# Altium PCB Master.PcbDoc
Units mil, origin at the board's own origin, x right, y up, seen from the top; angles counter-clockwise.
Board outline 3120.03 x 2730.03 mil, 2 copper layers (Top Layer, Bottom Layer); 69 components, 56 nets, 304 pads, 108 vias.
Unrouted connection lines stored in the file: 2.
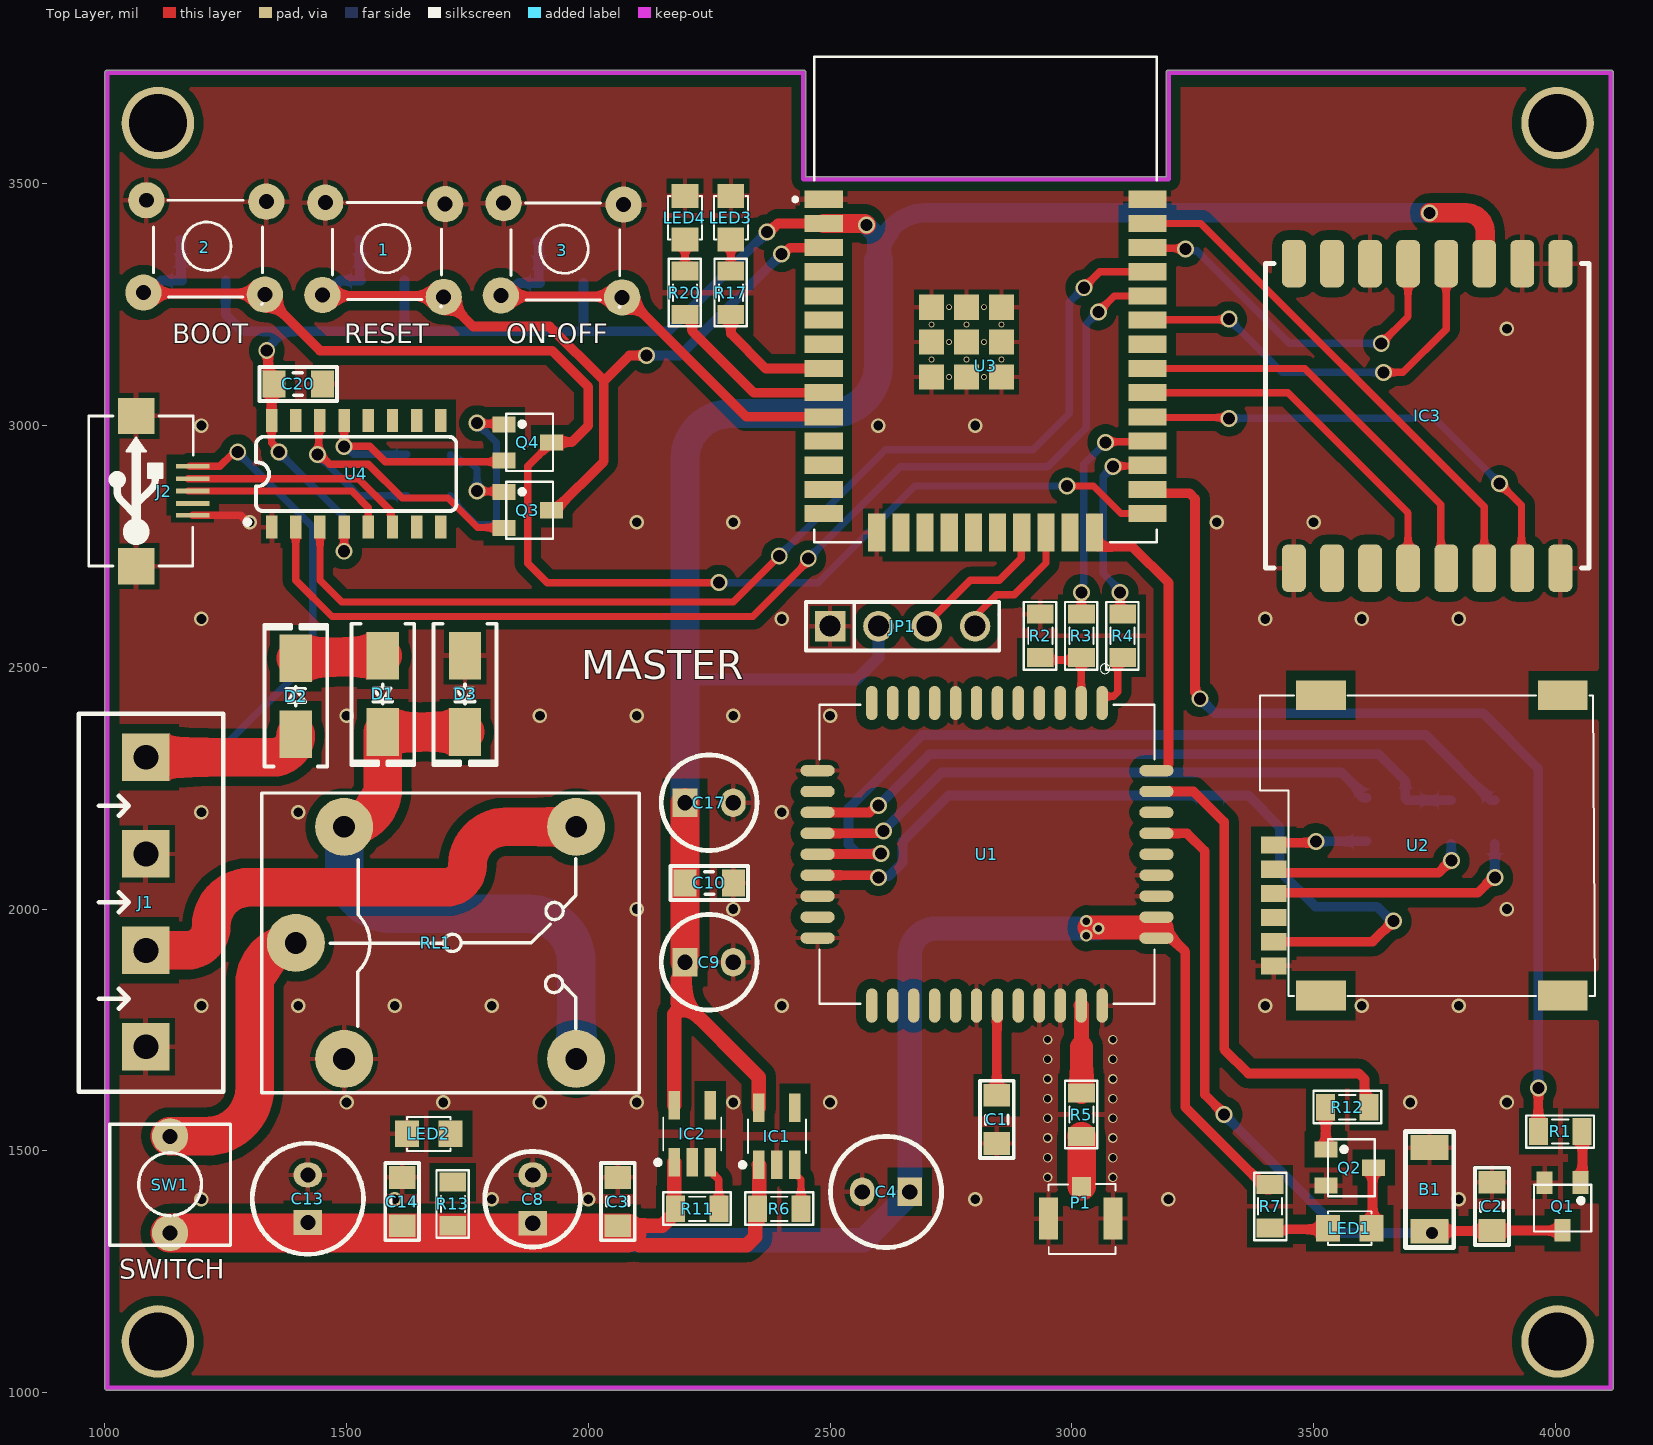
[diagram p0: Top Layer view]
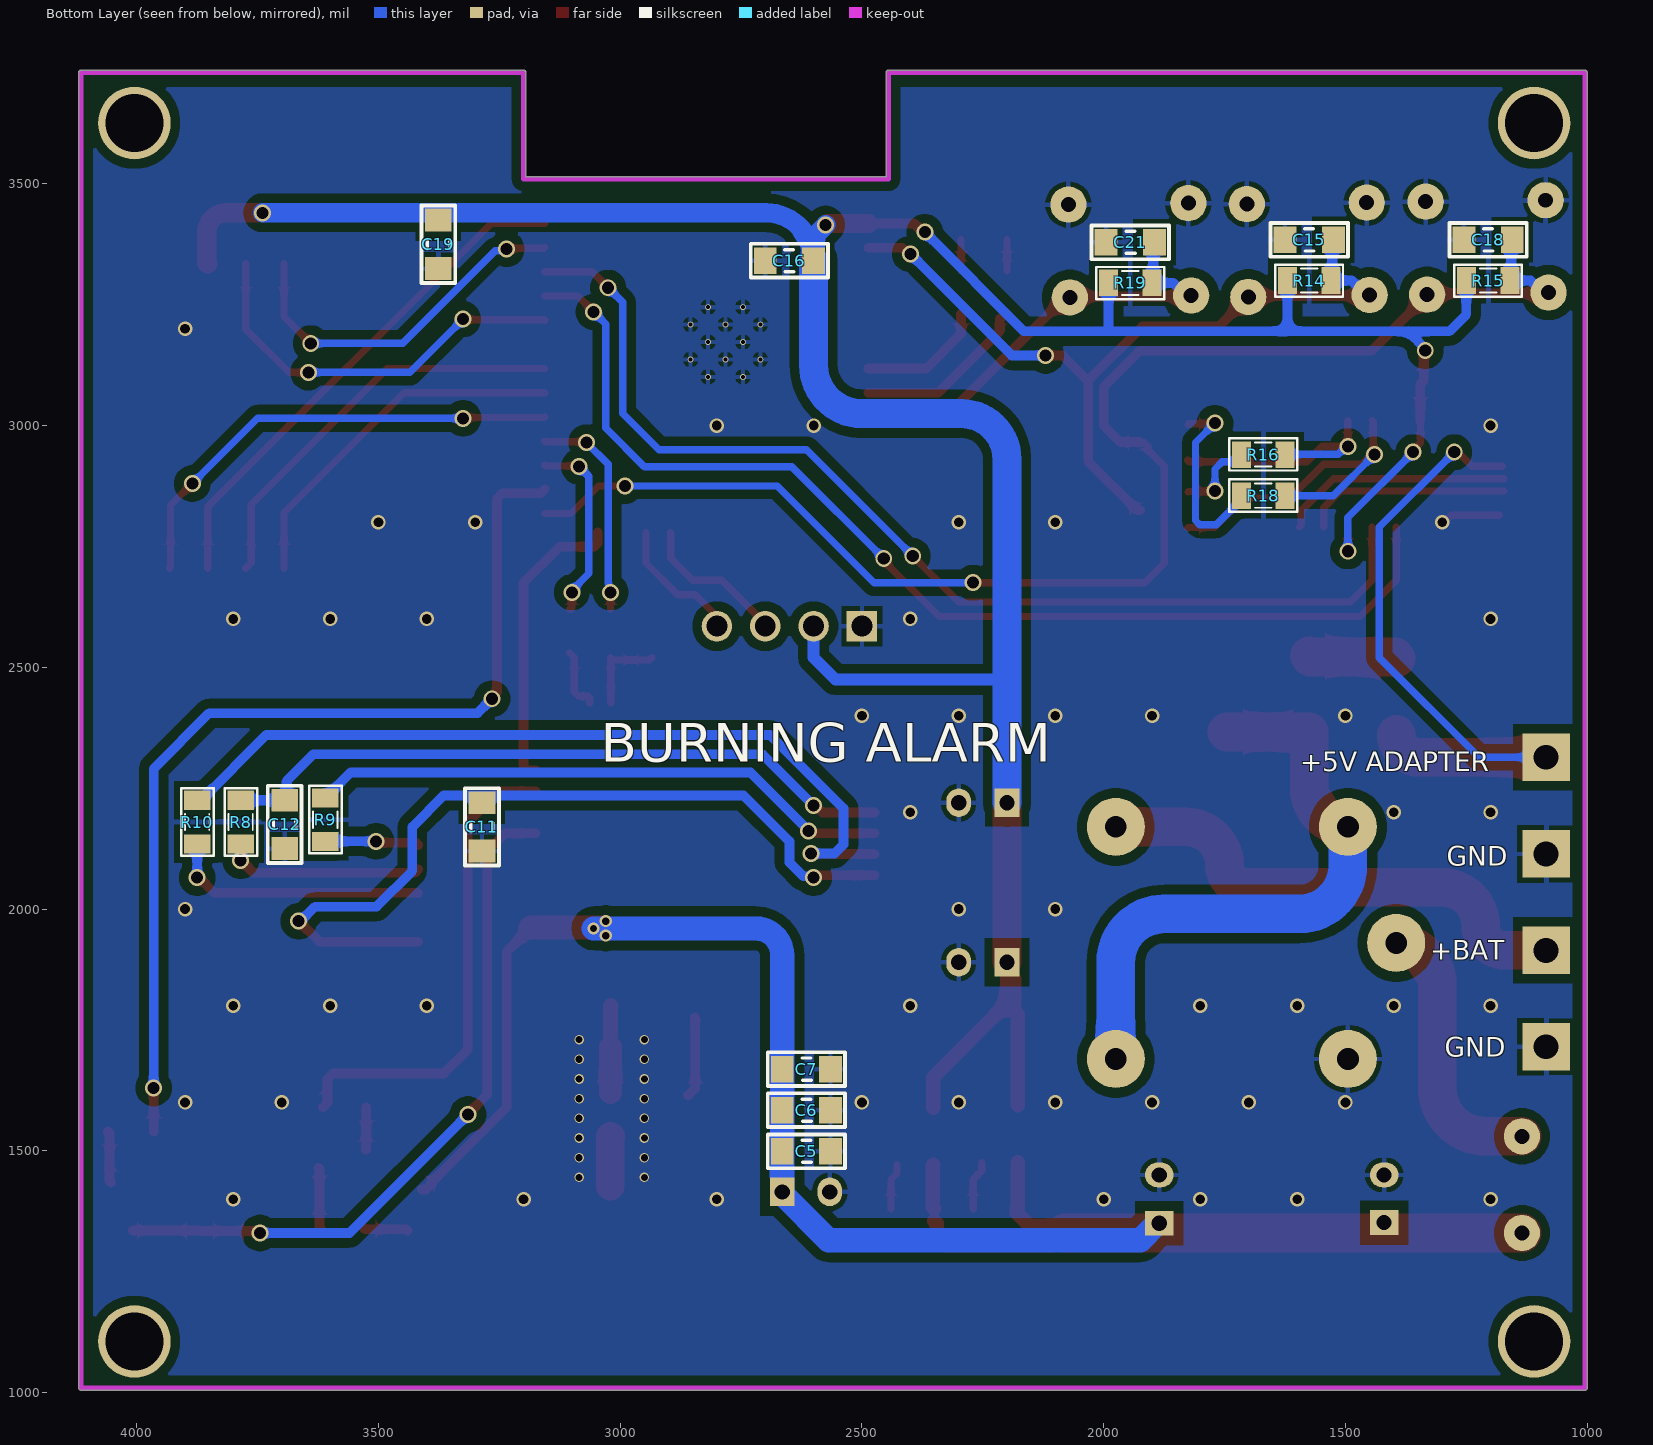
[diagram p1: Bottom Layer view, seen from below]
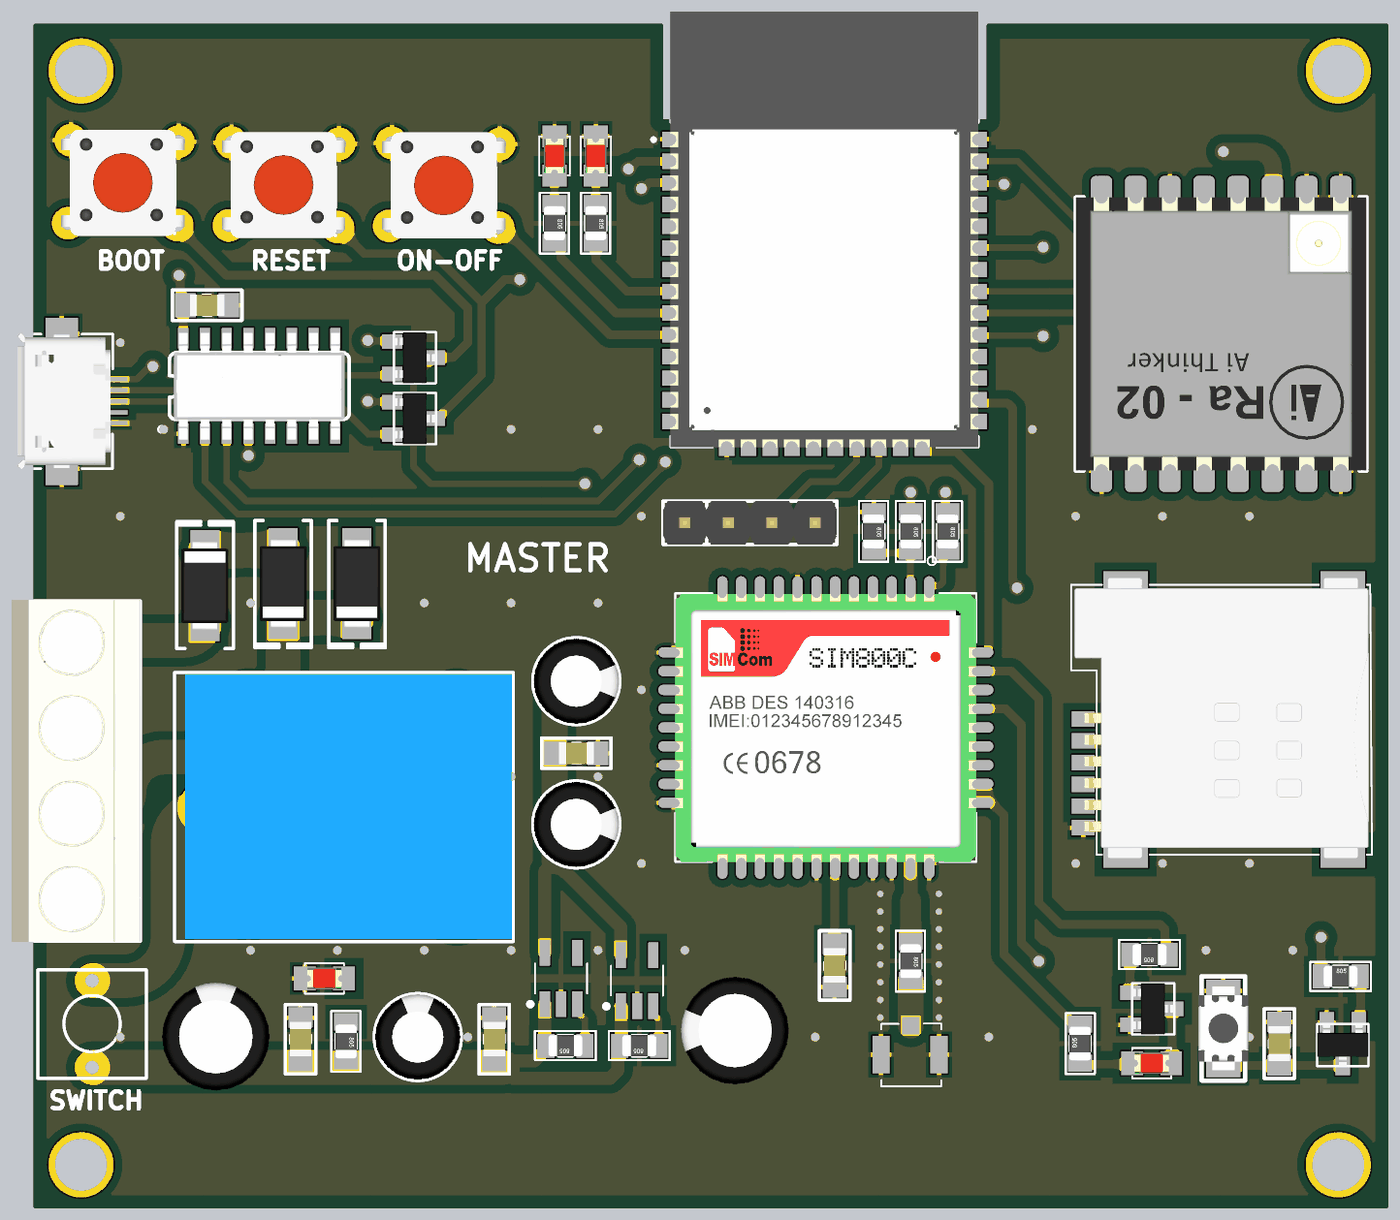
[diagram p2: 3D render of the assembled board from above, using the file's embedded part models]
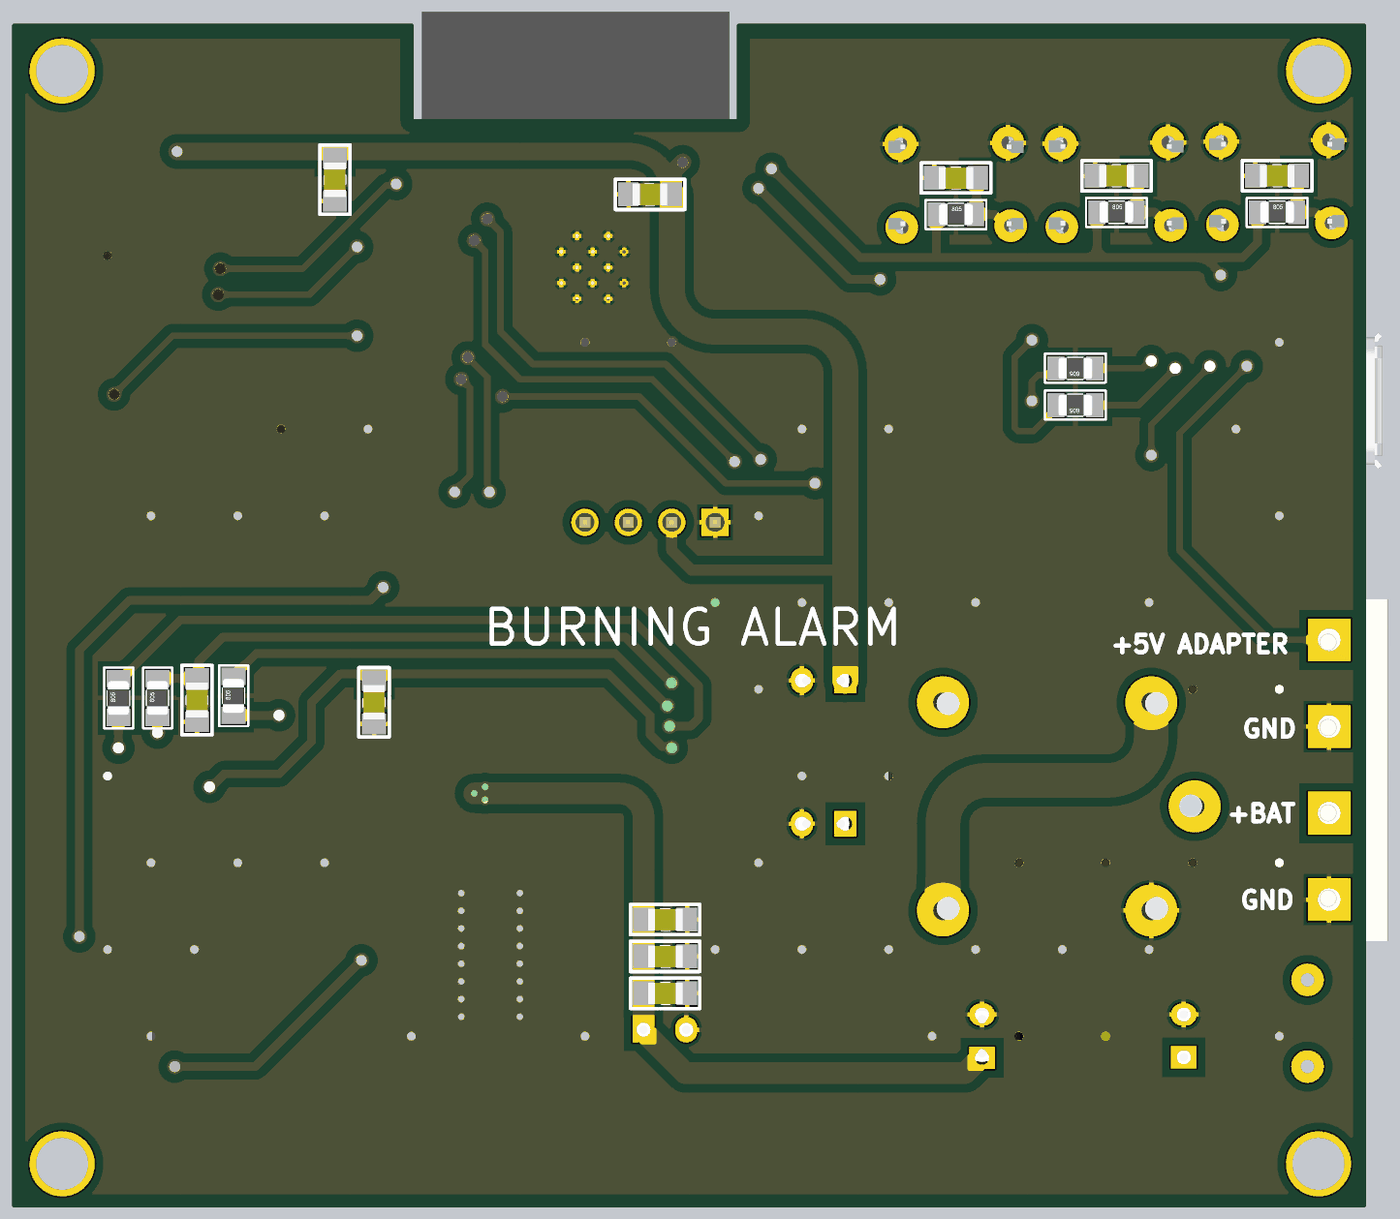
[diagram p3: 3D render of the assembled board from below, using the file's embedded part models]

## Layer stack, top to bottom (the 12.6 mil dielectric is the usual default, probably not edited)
Top Solder: solder mask 0.4, Solder Resist, Dk 3.5
Top Layer: signal copper 1.4
Dielectric 1: dielectric 12.6, FR-4, Dk 4.8
Bottom Layer: signal copper 1.4
Bottom Solder: solder mask 0.4, Solder Resist, Dk 3.5

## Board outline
999.99,1010 999.99,3730 cw(c1005,3730) 1005,3735.01 2160,3735.02 2445,3735.02 cw(c2445,3730) 2450.01,3730 2450.01,3515.01 3194.99,3515.01 3194.99,3730 cw(c3200,3730) 3200,3735.02 4115,3735.02 cw(c4115,3730) 4120.02,3730 4120.02,1010 cw(c4115,1010) 4115,1004.99 1005,1004.99 cw(c1005,1010)

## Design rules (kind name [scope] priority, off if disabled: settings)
Clearance [All] p1: gap=10 ignorepadtopadclearanceinfootprint=FALSE
PolygonConnect [All] p1: thpad.connectstyle=Relief thpad.reliefconductorwidth=10 thpad.reliefentries=4 thpad.polygonreliefangle="90 Angle" thpad.airgapwidth=10 smdpad.connectstyle=Relief smdpad.reliefconductorwidth=10 smdpad.reliefentries=4 smdpad.polygonreliefangle="90 Angle" smdpad.airgapwidth=10 via.connectstyle=Direct via.reliefconductorwidth=10 via.reliefentries=4 via.polygonreliefangle="90 Angle" via.airgapwidth=10
RoutingVias [All] p1: holewidth=20 width=30 viastyle="Through Hole" minholewidth=15 minwidth=15 maxholewidth=30 maxwidth=40
SolderMaskExpansion [All] p1: expansion=4 istentingtop=FALSE
Width [All] p1: maxlimit=100 minlimit=10 preferedwidth=15
30 further rules are at their usual default settings.

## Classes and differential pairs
component class Master: 1 2 3 B1 C1 C2 C3 C4 C5 C6 C7 C8 C9 C10 C11 C12 C13 C14 C15 C18 C20 D1 D2 D3 IC1 IC2 IC3 J1 J2 JP1 LED1 LED2 LED3 LED4 P1 Q1 Q2 Q3 Q4 R1 R2 R3 R4 R5 R6 R7 R8 R9 R10 R11 R12 R13 R14 R15 R16 R17 R18 R19 R20 RL1 SW1 U1 U2 U3 U4

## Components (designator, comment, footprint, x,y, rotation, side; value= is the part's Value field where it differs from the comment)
1 "SW" SW4 1456,3461 r0 top value="Button chip 4 pin"
2 "SW" SW4 1086,3466 r0 top value="Button chip 4 pin"
3 "SW" SW4 1825,3460 r0 top value="Button chip 4 pin"
B1 "Button 3x4x2.5" "Button 3x4x2.5" 3740,1420 r270 top
C1 "10nF" CAP_0805 2846,1565 r270 top value=33p
C2 "100nF" CAP_0805 3870,1385 r270 top value=33p
C3 "100nF" CAP_0805 2060,1395 r90 top value=33p
C4 "470uF" C8mm 2615.79,1415 r180 top
C5 "1uF" CAP_0805 2615,1500 r180 bottom value=33p
C6 "33pF" CAP_0805 2615,1585 r180 bottom value=33p
C7 "10pF" CAP_0805 2615,1670 r180 bottom value=33p
C8 "100uF" C5mm 1885,1400 r90 top
C9 "100uF" C5mm 2250,1890 r0 top
C10 "100nF" CAP_0805 2250,2055 r0 top value=33p
C11 "100nF" CAP_0805 3285,2170 r270 bottom value=33p
C12 "22pF" CAP_0805 3695,2175 r90 bottom value=33p
C13 "470uF" C8mm 1420,1400.79 r90 top
C14 "100nF" CAP_0805 1614,1395 r90 top value=33p
C15 "100nF" CAP_0805 1575,3385 r180 bottom value=33p
C16 "100nF" CAP_0805 2650,3340 r0 bottom value=33p
C17 "100uF" C5mm 2250,2220 r0 top
C18 "100nF" CAP_0805 1205,3385 r180 bottom value=33p
C19 "100nF" CAP_0805 3375,3375 r270 bottom value=33p
C20 "100nF" CAP_0805 1400,3085 r180 top value=33p
C21 "100nF" CAP_0805 1945,3380 r180 bottom value=33p
D1 "SS34 Diode 3A 40V" "DIODE SMA" 1575,2445 r270 top
D2 "SS34 Diode 3A 40V" "DIODE SMA" 1395,2440 r90 top
D3 "M7" "DIODE SMA" 1745,2445 r270 top
IC1 "RT9013" SOT23-5 2390,1530 r90 top
IC2 "RT9013" SOT23-5 2215,1535 r90 top
IC3 "LoRa-02" LoRa-02 3735,3020 r270 top
J1 "KF4" KF4-5.08 1085,2314 r270 top
J2 "USB-5" USB-M1 1181.84,2864.49 r90 top
JP1 "JP 1x4 2.54" "JP 1x4 DT" 2500,2585 r0 top
LED1 "LED" LED-0805-Red 3530,1340 r0 top value="LED 3 ly Single Colour"
LED2 "LED" LED-0805-Red 1715,1535 r180 top value="LED 3 ly Single Colour"
LED3 "LED-WIFI" LED-0805-Red 2295,3385 r90 top value="LED 3 ly Single Colour"
LED4 "LED-ONOFF" LED-0805-Red 2200,3385 r90 top value="LED 3 ly Single Colour"
P1 "Antenna" IPXS 3020,1410 r90 top
Q1 "C1815" SOT23D 4015,1385 r180 top
Q2 "C1815" SOT23D 3575,1465 r270 top
Q3 "C1815" SOT23D 1875,2825 r270 top
Q4 "C1815" SOT23D 1875,2965 r270 top
R1 "10k" RES-SMD-0805 4010,1540 r0 top
R2 "5.6k" RES-SMD-0805 2935,2565 r270 top
R3 "1k" RES-SMD-0805 3020,2565 r270 top
R4 "1k" RES-SMD-0805 3105,2565 r270 top
R5 "0R" RES-SMD-0805 3020,1575 r270 top
R6 "10k" RES-SMD-0805 2395,1380 r180 top
R7 "1k" RES-SMD-0805 3410,1385 r90 top
R8 "51R" RES-SMD-0805 3785,2180 r90 bottom
R9 "51R" RES-SMD-0805 3610,2185 r90 bottom
R10 "51R" RES-SMD-0805 3875,2180 r90 bottom
R11 "10k" RES-SMD-0805 2225,1380 r180 top
R12 "1k" RES-SMD-0805 3570,1590 r180 top
R13 "1k" RES-SMD-0805 1720,1390 r270 top
R14 "10k" RES-SMD-0805 1575,3300 r180 bottom
R15 "10k" RES-SMD-0805 1205,3300 r180 bottom
R16 "10k" RES-SMD-0805 1670,2940 r0 bottom
R17 "1k" RES-SMD-0805 2295,3275 r270 top
R18 "10k" RES-SMD-0805 1670,2855 r0 bottom
R19 "10k" RES-SMD-0805 1945,3295 r180 bottom
R20 "1k" RES-SMD-0805 2200,3275 r270 top
RL1 "Relay 10A/12V" "RELAY 5" 1720,1930 r0 top value="Relay SPDT, 10A, 12V"
SW1 "SW" SW2 1135,1530 r270 top value="SW chip 2 pin"
U1 "SIM800C" SIM800C 2830.43,2123.43 r270 top
U2 "SIM-KF016" "Sim Socket" 3720,2135 r90 top value="Sim holder"
U3 "ESP32-WROOM-32" MODULE_ESP32-WROOM-32 2821.61,3260.94 r0 top
U4 "CH340C" SO016 1520,2900.24 r0 top

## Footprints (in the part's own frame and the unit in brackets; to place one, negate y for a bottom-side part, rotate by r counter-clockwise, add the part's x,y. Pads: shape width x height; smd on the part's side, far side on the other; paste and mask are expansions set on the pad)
"Button 3x4x2.5" [mm]
  rect 1.3x2 smd: 1(-2.2,0) 2(2.2,0)
  silkscreen extent -3.05,-1.27 3.05,1.27, body extent -2.45,-1.45 2.45,1.45, height 2
C5mm [mm]
  rect 1.3x1.5 hole 0.8: 1(-1.27,0)
  oval 1.3x1.5 hole 0.8: 2(1.27,0)
  silkscreen extent -2.51,-2.51 2.51,2.51, body extent -2.5,-2.5 2.49,2.5, height 11.01
C8mm [mm]
  rect 1.3x1.5 hole 0.8: 1(-1.25,0)
  oval 1.3x1.5 hole 0.8: 2(1.25,0)
  silkscreen extent -2.92,-2.92 2.92,2.92, body extent -3.15,-3.15 3.16,3.15, height 11.51
CAP_0805 [mm]
  rect 1.2x1.4 smd: 1(-1.27,-0.025) 2(1.27,-0.025)
  silkscreen extent -2.03,-0.91 2.03,0.86, body extent -1.01,-0.66 1.01,0.61, height 0.61
"DIODE SMA" [mm] "SMA"
  rect 2.5x1.7 smd: 1(-2,0) 2(2,0)
  silkscreen extent -3.68,-1.65 3.75,1.65, body extent -2.6,-1.37 2.6,1.37, height 2.4
IPXS [mm] "SOT 23 _ 1-3-2"
  rect 1x1 smd: 1(0.415,-0.01)
  rect 2.2x1 smd: 2(-1.273,-1.658) 3(-1.278,1.73)
  silkscreen extent -3.13,-1.79 0.53,1.73, body extent -2.83,-1.49 0.31,1.56, height 1.55
"JP 1x4 DT" [mm] "4 pins, 1 row, straight, gold plating"
  rect 1.6x1.6 hole 1.1: 1(0,0)
  round 1.6 hole 1.1: 2(2.54,0) 3(5.08,0) 4(7.62,0)
  silkscreen extent -1.27,-1.27 8.89,1.27, body extent -1.27,-1.27 8.89,1.27, height 8.54
KF4-5.08 [mm]
  rect 2.5x2.5 hole 1.3: 1(0,0) 2(5.08,0) 3(10.147,0) 4(15.215,0)
  silkscreen extent -2.29,-3.53 17.58,4.06, body extent -2.36,-3.43 17.64,4.07, height 10
LED-0805-Red [mil]
  rect 50x55 smd: 1(0,0) 2(90,0)
  silkscreen extent 0,-35 90,35, body extent 5,-25 85,25, height 43
LoRa-02 [mm]
  rrect50% 2.5x1.25 smd: 1(-8,7) 2(-8,5) 2(-8,-3) 3(-8,3) 4(-8,1) 5(-8,-1) 7(-8,-5) 8(-8,-7) 9(8,-7) 10(8,-5) 11(8,-3) 12(8,-1) 13(8,1) 14(8,3) 15(8,5) 16(8,7)
  silkscreen extent -8,-8.5 8,8.5, body extent -8,-8.5 8,8.5, height 3.03
MODULE_ESP32-WROOM-32 [mm]
  rect 2x0.9 smd: 1(-8.5,5.26) 2(-8.5,3.99) 3(-8.5,2.72) 4(-8.5,1.45) 5(-8.5,0.18) 6(-8.5,-1.09) 7(-8.5,-2.36) 8(-8.5,-3.63) 9(-8.5,-4.9) 10(-8.5,-6.17) 11(-8.5,-7.44) 12(-8.5,-8.71) 13(-8.5,-9.98) 14(-8.5,-11.25) 25(8.5,-11.25) 26(8.5,-9.98) 27(8.5,-8.71) 28(8.5,-7.44) 29(8.5,-6.17) 30(8.5,-4.9) 31(8.5,-3.63) 32(8.5,-2.36) 33(8.5,-1.09) 34(8.5,0.18) 35(8.5,1.45) 36(8.5,2.72) 37(8.5,3.99) 38(8.5,5.26)
  rect 0.9x2 smd: 15(-5.715,-12.25) 16(-4.445,-12.25) 17(-3.175,-12.25) 18(-1.905,-12.25) 19(-0.635,-12.25) 20(0.635,-12.25) 21(1.905,-12.25) 22(3.175,-12.25) 23(4.445,-12.25) 24(5.715,-12.25)
  rect 1.33x1.33 smd: 39_1(-2.835,-0.405) 39_2(-1,-0.405) 39_3(0.835,-0.405) 39_4(-2.835,-2.24) 39_5(-1,-2.24) 39_6(0.835,-2.24) 39_7(-2.835,-4.075) 39_8(-1,-4.075) 39_9(0.835,-4.075)
  round 0.3 hole 0.2: 39_10(-1.917,-0.405) 39_11(-0.082,-0.405) 39_12(-2.835,-1.322) 39_13(-1,-1.322) 39_14(0.835,-1.322) 39_15(-1.917,-2.24) 39_16(-0.082,-2.24) 39_17(-2.835,-3.157) 39_18(-1,-3.157) 39_19(0.835,-3.157) 39_20(-1.917,-4.075) 39_21(-0.082,-4.075)
  silkscreen extent -10.1,-12.75 9,12.75, body extent -9.02,-12.75 8.98,12.75, height 3.2
"RELAY 5" [mil] "Reley DPDT, 8 pin, 1A, W400mil, L800mil,H 300mil"
  round 120 hole 45: 1(-325,0) 2(255,240) 3(255,-240) 4(-225,-240) 5(-225,240)
  silkscreen extent -395,-310 385,310, body extent -371,-304 381,306, height 602
RES-SMD-0805 [mil]
  rect 39.37x55 smd: 1(-45,0) 2(45,0)
  silkscreen extent -70,-34 70,33, body extent -39,-25 39,25, height 31
SIM800C [mm]
  oval 1.8x0.6 smd: 1(-7.691,5.902) 2(-7.691,4.802) 3(-7.691,3.702) 4(-7.691,2.602) 5(-7.691,1.502) 6(-7.691,0.402) 7(-7.691,-0.698) 8(-7.691,-1.798) 9(-7.691,-2.898) 10(-7.691,-3.998) 11(-7.691,-5.098) 12(-7.691,-6.198) 22(8.209,-6.198) 23(8.209,-5.098) 24(8.209,-3.998) 25(8.209,-2.898) 26(8.209,-1.798) 27(8.209,-0.698) 28(8.209,0.402) 29(8.209,1.502) 30(8.209,2.602) 31(8.209,3.702) 32(8.209,4.802) 33(8.209,5.902)
  oval 0.6x1.8 smd: 13(-4.141,-9.048) 14(-3.041,-9.048) 15(-1.941,-9.048) 16(-0.841,-9.048) 17(0.259,-9.048) 18(1.359,-9.048) 19(2.459,-9.048) 20(3.559,-9.048) 21(4.659,-9.048) 34(4.659,8.752) 35(3.559,8.752) 36(2.459,8.752) 37(1.359,8.752) 38(0.259,8.752) 39(-0.841,8.752) 40(-1.941,8.752) 41(-3.041,8.752) 42(-4.141,8.752)
  silkscreen extent -9.74,-8.95 8.11,8.65, body extent -7.57,-8.95 8.13,8.65, height 2.31
"Sim Socket" [mm] "Socket Micro Sim 6P Push"
  rect 0.9x1.35 smd: 1(-5.145,7.685) 2(-2.605,7.685) 3(-0.065,7.685) 5(-6.415,7.685) 6(-3.875,7.685) 7(-1.335,7.685)
  rect 1.56x2.61 smd: ""(-7.975,-7.5) ""(-7.975,5.2) ""(7.805,-7.5) ""(7.805,5.2)
  silkscreen extent -8,-9.2 7.8,8.4, body extent -8.2,-9 8.2,8.2, height 1.35
SO016 [mm]
  rect 0.6x1.2 smd: 1(-4.445,-2.8) 2(-3.175,-2.8) 3(-1.905,-2.8) 4(-0.635,-2.8) 5(0.635,-2.8) 6(1.905,-2.8) 7(3.175,-2.8) 8(4.445,-2.8) 9(4.445,2.8) 10(3.175,2.8) 11(1.905,2.8) 12(0.635,2.8) 13(-0.635,2.8) 14(-1.905,2.8) 15(-3.175,2.8) 16(-4.445,2.8)
  silkscreen extent -5.84,-2.67 5.26,1.95, body extent -4.99,-3.13 4.99,3.1, height 1.58
SOT23-5 [mm] "SOT23, 5-Leads, Body 3.0x3.0mm (max), Pitch 0.95mm, IPC Medium Density"
  rect 1.5x0.6 smd: 1(-1.5,0.95) 2(-1.5,0) 3(-1.5,-0.95) 4(1.5,-0.95) 5(1.5,0.95)
  silkscreen extent -1.62,-1.52 0.87,1.92, body extent -1.75,-1.52 1.75,1.53, height 1.45
SOT23D [mm] "SOT 23C - 1-3-2 - BCE"
  rect 0.85x1.2 smd: 1(-0.95,-1.25) 2(0.94,-1.245) 3(0,1.25)
  silkscreen extent -1.5,-1.14 1.5,1.32, body extent -1.5,-1.17 1.5,1.33, height 1.06
SW2 [mil] "SW button 2pin, 250x 250 mil"
  round 75 hole 31: 1(0,0) 2(200,0)
  silkscreen extent -25,-125 225,125
SW4 [mil] "SW button 4pin, 250 x250 mil"
  round 75 hole 31: 1(0,0) 2(245,-195) 3(248,-3) 4(-6,-191)
  silkscreen extent 15,-215 240,0, body extent -36,-220 276,24, height 276
USB-M1 [mil]
  rect 10x70 smd: 1(51.18,0) 2(25.59,0) 3(0,0) 4(-25.59,0) 5(-50,0)
  rect 74.8x74.8 smd: 5(-155.51,116.84) 5(155.51,116.84)
  silkscreen extent -155,-1 155,215, body extent -157,5 158,218, height 107

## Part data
1 2 3: library part SW4, "Switch button 4 pin"
C1 C2 C3 C5 C6 C7 C10 C11 C12 C14 C15 C16 C18 C19 C20 C21: library part CapSMD, "Capacitor"
C4 C13: library part "Cap Pol", "470uF 16V"
C8 C9 C17: library part "Cap Pol", "100uF 16V"
D1 D2 D3: library part "Diode M7 ( 4007 )", "Dán"
IC1 IC2: "RT9013-33GB IC REG LINEAR 3.3V 500mA SOT23-5"
J1: Manufacturer="W¨¹rth Elektronik eiSos GmbH", partNo=691133710004
J2: Manufacturer=FCI, Manufacturer Part Number=10118193-0001LF, Supplier Part Number 1=609-4616-1-ND
JP1: library part "JP 1x4 2.54 Duc Thang", "Cắm"
LED1 LED2: "LED Single colour Green and Red"
LED3 LED4: library part LED, "LED Single colour Green and Red"
P1: library part IPXSx66, "Antenna GSM GPS"
Q1 Q2 Q3 Q4: library part 2SC1815, "NPN 600mW, ECB"
R1 R2 R3 R4 R5 R6 R7 R8 R9 R10 R11 R12 R13 R14 R15 R16 R17 R18 R19 R20: library part "Resistor - SMD", "Resistor", Manufacturer="Generic Components"
RL1: library part "Relay 5", "Relay SPDT,10A - 12VDC 5 Pin"
SW1: library part SW2, "Switch button 2 pin"
U2: library part "Sim holder", "SIM Card Holder KF-016"
U3: "Bluetooth, WiFi Transceiver Module 2.4GHz ~ 2.5GHz Surface Mount", Package="Module Espressif Systems"
U4: "USB to serial chip CH340", Package=Package

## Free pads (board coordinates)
  round 150 hole 120: 0(1109.69,1105.69) 0(1109.69,3625.69) 0(4004.69,1105.69) 0(4004.69,3625.69)

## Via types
v1: diameter 30, hole 20, Top Layer to Bottom Layer, tented both sides, 48 vias
v2: diameter 35, hole 25, Top Layer to Bottom Layer, tented both sides, 41 vias
v3: diameter 20, hole 15, Top Layer to Bottom Layer, tented both sides, 16 vias
v4: diameter 25, hole 15, Top Layer to Bottom Layer, tented both sides, 3 vias

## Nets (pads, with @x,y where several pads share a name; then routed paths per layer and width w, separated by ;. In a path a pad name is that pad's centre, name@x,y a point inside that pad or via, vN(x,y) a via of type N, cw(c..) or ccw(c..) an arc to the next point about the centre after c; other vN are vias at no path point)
+3.3V: C9.1 C10.1 C16.1 C17.1 C19.1 C20.2 IC1.5 IC2.5 IC3.3 JP1.2 R14.1 R15.1 R19.1 U3.2 U4.4 U4.16 | length 6680.6
  Top Layer w15: U4.16 1345,2964.35 1360,2949.35 v2(1360,2945) ; v2(1495,2740) U4.4
  Top Layer w20: v2(1335,3155) 1337.87,3152.13 1337.87,3093.13 1345,3086 U4.16 ; v2(2370,3400) 2374.06,3400 2392.09,3418.03 U3.2
  Top Layer w30: IC2.5 2177.6,1782.6 2200,1805 ; 2185,1805 2185,1856.06 2189.41,1860.47 2189.41,1879.41 C9.1 ; 2200,1856.06 2200,1805 ; IC1.5 2352.6,1652.4 2200,1805
  Top Layer w40: U3.2 2571.97,3418.03 v2(2575,3415) ; v2(3740,3440) 3815,3440 cw(c3815,3400) 3855,3400 3855,3336.85 cw(c3853.11,3336.85) IC3.3
  Top Layer w60: C9.1 C10.1 C17.1
  Bottom Layer w15: v2(1360,2945) 1495,2810 v2(1495,2740)
  Bottom Layer w20: R15.1 1250,3230 1285,3195 1370,3195 ; v2(1335,3155) 1335,3159.06 1350,3174.06 1350,3175 1370,3195 ; R14.1 1620,3195 ; R19.1 1990,3200 1985,3195 ; v2(2370,3400) 2165,3195 1985,3195 ; 1370,3195 1620,3195 ; 1620,3195 1985,3195
  Bottom Layer w25: 2200,2475 2555,2475 2600,2520 JP1.2
  Bottom Layer w30: 3650,3445 3655,3440
  Bottom Layer w40: v2(2575,3415) 2596.38,3393.62 2596.38,3344.62 C16.1 cw(c2699,3341) 2699,3440 3655,3440 v2(3740,3440)
  Bottom Layer w60: C17.1 2200,2475 2200,2930 cw(c2294.6,2930) 2294.6,3024.6 2500,3024.6 ccw(c2500,3124.6) 2600,3124.6 C16.1
+4.2V: D1.2 D3.2 RL1.3 RL1.5 | length 1307.7
  Top Layer w80: RL1.5@1495,2180.82 RL1.5 ccw(c1495,2250) 1575,2250 D1.2 D3.2
  Bottom Layer w80: RL1.5@1505.82,2170 RL1.5 1495,2090 ccw(c1595,2090) 1595,1990 1875,1990 cw(c1875,1890) 1975,1890 RL1.3
+5: D2.1 J1.1 J2.1 | length 1368.7
  Top Layer w15: J2.1@1175,2915.67 J2.1 1237.93,2915.67 1263.44,2941.17 1271.17,2941.17 v2(1275,2945)
  Top Layer w80: J1.1 1347.74,2314 ccw(c1347.74,2361.26) D2.1
  Bottom Layer w15: J1.1 1224,2314 1430,2520 1430,2790 v2(1275,2945)
+VBAT: J1.3 RL1.2 | length 1035.8
  Top Layer w80: J1.3 1169.5,1914.5 ccw(c1169.5,1965) 1220,1965 cw(c1300,1965) 1300,2045 1705,2045 ccw(c1705,2090) 1750,2090 cw(c1830,2090) 1830,2170 RL1.2
BT_ONOFF: 3.2 3.4 C21.2 R19.2 U3.10 | length 954
  Top Layer w20: 3.4 1821,3267 3.2@2068,3267 ; 3.2 2080,3265 2326.97,3018.03 U3.10
  Bottom Layer w15: C21.2 C21.2@1900,3384
  Bottom Layer w20: 3.4 1830.12,3269 1856.12,3295 R19.2 1897.5,3297.5 1897.5,3376.5 C21.2
CH340_RXD: U3.35 U4.3 | length 2257.8
  Top Layer w15: U4.3 1445,2680 1490,2635 2300,2635 v2(2395,2730) ; v2(3025,3285) 3058.03,3318.03 U3.35
  Bottom Layer w15: v2(2395,2730) 2395,2730.36 2614.64,2950 2920,2950 2995,3025 2995,3255 v2(3025,3285)
CH340_TXD: U3.34 U4.2 | length 2305.8
  Top Layer w15: U4.2 1395,2680 1470,2605 2340,2605 2455,2720 v2(2455,2725) ; v2(3055,3235) 3088.03,3268.03 U3.34
  Bottom Layer w15: v2(2455,2725) 2645,2915 2950,2915 3030,2995 3030,3210 v2(3055,3235)
D_N: J2.2 U4.6 | length 482.2
  Top Layer w15: J2.2@1171.84,2890.08 1524.92,2890.08 1591.37,2823.63 1591.37,2793.63 U4.6
D_P: J2.3 U4.5 | length 427.4
  Top Layer w15: J2.3@1171.84,2864.49 1510.51,2864.49 1545,2830 U4.5
DTR: Q4.2 R16.1 U4.13 | length 538.8
  Top Layer w15: U4.13 1495,2955 1497,2957 1548,2957 1580,2925 1823,2925 Q4.2
  Bottom Layer w15: v2(1495,2957) 1498.41,2957 1515,2940.41 1624.59,2940.41 R16.1
EN: 1.2 1.4 C15.2 Q3.3 R14.2 U3.3 | length 1720
  Top Layer w20: 1.4 1452,3268 1699,3268 1.2 1762,3205 1920.25,3205 2032,3093.25 2032,2925.9 1931.1,2825 Q3.3 ; 2032,3092 2085,3145 v2(2120,3145) ; v2(2400,3355) 2404.06,3355 2417.09,3368.03 U3.3
  Bottom Layer w20: 1.4 1457.12,3270 1487.12,3300 R14.2 1527.5,3302.5 1527.5,3381.5 C15.2 ; v2(2120,3145) 2190,3145 v2(2400,3355)
ESP_PWRKEY: R1.1 U3.26 | length 2034.6
  Top Layer w20: U3.26 3163.98,2860.31 3243.28,2860.31 3255,2848.6 3255,2449.06 3265,2439.06 v2(3265,2435) ; R1.1 v2(3965,1630)
  Bottom Layer w20: v2(3265,2435) 3295,2405 3850,2405 3965,2290 v2(3965,1630)
GND: 1.1 1.3 2.1 2.3 3.1 3.3 B1.1 C1.2 C2.1 C3.2 C4.2 C5.2 C6.2 C7.2 C8.2 C9.2 C10.2 C11.2 C12.1 C13.2 C14.2 C15.1 C16.2 C17.2 C18.1 C19.2 C20.1 C21.1 D3.1 IC1.2 IC2.2 IC3.1 IC3.2 IC3.9 IC3.16 J1.2 J1.4 J2.5 JP1.1 LED2.2 LED3.2 LED4.2 P1.2 P1.3 Q1.2 Q2.2 R2.1 RL1.4 U1.8 U1.13 U1.19 U1.21 U1.27 U1.30 U1.31 U1.33 U1.36 U1.37 U2.5 U3.1 U3.15 U3.38 U3.39_1 U3.39_2 U3.39_3 U3.39_4 U3.39_5 U3.39_6 U3.39_7 U3.39_8 U3.39_9 U3.39_10 U3.39_11 U3.39_12 U3.39_13 U3.39_14 U3.39_15 U3.39_16 U3.39_17 U3.39_18 U3.39_19 U3.39_20 U3.39_21 U4.1 | length 124.2
  Top Layer w15: J2.5@1181.84,2814.49 1281.45,2814.49 1295.94,2800 v1(1300,2800)
  other v1: 1200,1400 1600,1400 1800,1400 2000,1400 2800,1400 3200,1400 3800,1400 1500,1600 1700,1600 1900,1600 2100,1600 2300,1600 2500,1600 3700,1600 3900,1600 1200,1800 1400,1800 1600,1800 1800,1800 2400,1800 3400,1800 3600,1800 3800,1800 2100,2000 2300,2000 3900,2000 1200,2200 1400,2200 2400,2200 1500,2400 1900,2400 2100,2400 2300,2400 2500,2400 1200,2600 2400,2600 3400,2600 3600,2600 3800,2600 2100,2800 2300,2800 3300,2800 3500,2800 1200,3000 2600,3000 2800,3000 3900,3200
  other v3: 2950,1445 3085,1445 2950,1485.71 3085,1485.71 2950,1526.43 3085,1526.43 2950,1567.14 3085,1567.14 2950,1607.86 3085,1607.86 2950,1648.57 3085,1648.57 2950,1689.29 3085,1689.29 2950,1730 3085,1730
I2C_SCL: JP1.4 U3.22 | length 275.5
  Top Layer w15: JP1.4 2809.18,2594.18 2809.18,2614.18 2845,2650 2881.01,2650 2946.61,2715.61 U3.22
I2C_SDA: JP1.3 U3.21 | length 310.2
  Top Layer w15: JP1.3 2700,2590 2790,2680 2850,2680 2895.58,2725.58 2895.58,2777.63 U3.21
IO0: 2.2 2.4 C18.2 Q4.3 R15.2 U3.25 | length 3024.5
  Top Layer w15: Q4.3 1917.32,2965 1908.09,2955.77 1908.09,2948.88 1875,2915.79 1875,2715 1915,2675 v2(2270,2675) ; v2(2990,2875) 3045,2875 3101.97,2818.03 U3.25
  Top Layer w20: 2.4@1082,3273 1329,3273 2.2 1331,3269 1445,3155 1925,3155 2000,3080 2000,3000 1966,2966 1925.21,2966 Q4.3
  Bottom Layer w15: v2(2270,2675) 2475,2675 2675,2875 v2(2990,2875)
  Bottom Layer w20: 2.4 1092.12,3275 1117.12,3300 R15.2 1157.5,3302.5 1157.5,3381.5 C18.2
LORA_IO0: IC3.5 U3.36 | length 753.8
  Top Layer w15: U3.36 3157.78,3366.52 3233.48,3366.52 v2(3235,3365) ; v2(3640,3170) 3695.63,3225.63 IC3.5
  Bottom Layer w15: v2(3235,3365) 3238.28,3361.72 3258.28,3361.72 3450,3170 v2(3640,3170)
LORA_MISO: IC3.13 U3.31 | length 859.8
  Top Layer w15: U3.31 3481.97,3118.03 3763.25,2836.75 3763.25,2716.16 IC3.13
LORA_MOSI: IC3.14 U3.37 | length 1066.5
  Top Layer w15: U3.37 3266.97,3418.03 3853.11,2831.89 IC3.14
LORA_NSS: IC3.15 U3.29 | length 980.3
  Top Layer w15: U3.29 3157.78,3016.52 3323.48,3016.52 v2(3325,3015) ; v2(3885,2880) 3930,2835 3930,2706.89 IC3.15
  Bottom Layer w15: v2(3325,3015) 3750,3015 v2(3885,2880)
LORA_RST: IC3.4 U3.33 | length 837.1
  Top Layer w15: U3.33 3157.24,3219.02 3324.02,3219.02 v2(3325,3220) ; v2(3645,3110) 3685,3110 3774.37,3199.37 IC3.4
  Bottom Layer w15: v2(3325,3220) 3435,3110 v2(3645,3110)
LORA_SCK: IC3.12 U3.30 | length 756.7
  Top Layer w15: U3.30 3446.97,3068.03 3695.63,2819.37 IC3.12
NetC1_1: C1.1 U1.28 | length 168.1
  Top Layer w20: U1.28@2846.04,1775.63 2846.04,1775.41 2845,1774.37 2845,1628.62 2858.62,1615 C1.1@2860,1615
NetD1_1: D1.1 D2.2 | length 182.1
  Top Layer w80: D2.2 1397.5,2521.24 1572.5,2521.24 D1.1
NetIC1_3: IC1.3 R6.1 | length 96.2
  Top Layer w15: IC1.3 2427.4,1453.23 2440,1440.63 R6.1
NetIC2_3: IC2.3 R11.1 | length 103.2
  Top Layer w15: IC2.3 2252.4,1458.23 2270,1440.63 R11.1
NetLED1_1: LED1.1 R7.1 | length 92.1
  Top Layer w20: 3440,1335 3442.5,1337.5 3527.5,1337.5 LED1.1
NetLED1_2: LED1.2 Q2.3 | length 126.7
  Top Layer w20: LED1.2 3622.11,1342.11 3622.11,1462.89 Q2.3
NetLED2_1: LED2.1 R13.1
NetLED3_1: LED3.1 R17.1 | length 65
  Top Layer w15: R17.1 LED3.1
NetLED4_1: LED4.1 R20.1 | length 65
  Top Layer w15: R20.1 LED4.1
NetP1_1: P1.1 R5.2 | length 104.1
  Top Layer w59.06: R5.2 3020.39,1530 P1.1
NetQ1_1: Q1.1 R1.2 | length 108.9
  Top Layer w20: Q1.1 4056.2,1438.01 4056.2,1536.2 R1.2@4060,1540
NetQ2_1: Q2.1 R12.2 | length 87.9
  Top Layer w20: R12.2 3525.39,1589.61 3525.39,1502.79 Q2.1
NetQ3_1: Q3.1 R16.2 | length 170.9
  Top Layer w15: v2(1770,2865) 1771.3,2863.7 1824.49,2863.7 Q3.1
  Bottom Layer w15: R16.2 1715,2937.19 1727.19,2925 1755,2925 1770,2910 v2(1770,2865)
NetQ4_1: Q4.1 R18.2 | length 402.7
  Top Layer w15: v2(1770,3005) 1771.3,3003.7 1824.49,3003.7 Q4.1
  Bottom Layer w15: R18.2 1715,2847.19 1767.19,2795 1801.21,2795 1810,2803.79 1810,2965 v2(1770,3005)
NetR2_2: R2.2 R3.2 U1.2 | length 177.9
  Top Layer w15: R2.2 2940,2515 3015,2515 R3.2 ; U1.2 R3.2@3019.49,2515
NetR4_2: R4.2 U1.1 | length 132.6
  Top Layer w15: U1.1 3062.8,2436.02 3066.78,2440 3086.21,2440 3095,2448.79 3095,2520 R4.2@3105,2530
NetR5_1: R5.1 U1.32 | length 180.7
  Top Layer w31.5: U1.32 3020,1800.24 3020,1715
  Top Layer w47.24: R5.1 3020,1715
NetR8_1: R8.1 U2.7 | length 416
  Top Layer w20: U2.7 3424.88,2075 3758.34,2075 3783.34,2100 v2(3785,2100)
  Bottom Layer w20: v2(3785,2100) R8.1
NetR9_1: R9.1 U2.3 | length 195.7
  Top Layer w20: U2.3 3422.13,2137.13 3502.13,2137.13 v2(3505,2140)
  Bottom Layer w20: v2(3505,2140) R9.1
NetR10_1: R10.1 U2.2 | length 541
  Top Layer w20: U2.2 3418.72,2033.72 3839.66,2033.72 3870.94,2065 v2(3875,2065)
  Bottom Layer w20: v2(3875,2065) R10.1
NetR17_2: R17.2 U3.8 | length 261.8
  Top Layer w20: R17.2 2295,3190 2366.97,3118.03 U3.8
NetR20_2: R20.2 U3.9 | length 368.8
  Top Layer w20: R20.2 2205.12,3230 2214.8,3220.32 2214.8,3195.2 2341.97,3068.03 U3.9
NetRL1_1: RL1.1 SW1.1 | length 580.6
  Top Layer w80: SW1.1 1210,1530 ccw(c1210,1630) 1310,1630 1310,1845 cw(c1395,1845) RL1.1
RST: Q3.2 R18.1 U4.14 | length 741.7
  Top Layer w15: U4.14 1442.5,3007.97 1442.5,2942.5 v2(1440,2940) 1445.41,2940 1465.41,2920 1545,2920 1615,2850 1710,2850 1771,2789 1825,2789 Q3.2
  Bottom Layer w15: v2(1440,2940) 1525,2855 R18.1
SIM_CLK: R9.2 U1.16 | length 1214.6
  Top Layer w20: U1.16 2600.95,2156.54 2606.13,2161.71 v2(2610.19,2161.71)
  Bottom Layer w20: v2(2610.19,2161.71) 2610.19,2162.16 2730.55,2282.51 3557.49,2282.51 3592.5,2247.5 3592.5,2239.68 3602.19,2230 R9.2
SIM_DATA: C12.2 R8.2 U1.15 | length 1421
  Top Layer w20: U1.15 2581.64,2199.84 2596.37,2214.57 v2(2600.43,2214.57)
  Bottom Layer w20: v2(2600.43,2214.57) 2705.86,2320 3635,2320 3689.98,2265.02 3689.98,2229.02 C12.2 R8.2
SIM_NETLIGHT: R12.1 U1.41 | length 1014.3
  Top Layer w20: U1.41 3251.85,2243.15 3315,2180 3315,1710 3365,1660 3593.6,1660 3605.32,1648.28 3605.32,1599.69 R12.1
SIM_PWRKEY: B1.2 C2.2 Q1.3 U1.39 | length 1473.5
  Top Layer w20: U1.39 3238.46,2156.54 3275,2120 3275,1616.32 3315,1576.32 v2(3315,1575) ; v2(3745,1330) 3749.19,1334.19 3868.19,1334.19 C2.2 Q1.3@4008.27,1335
  Bottom Layer w20: v2(3315,1575) 3560,1330 v2(3745,1330)
SIM_RST: R10.2 U1.17 | length 1736.2
  Top Layer w20: U1.17 2474.91,2113.92 2603.92,2113.92 v2(2605,2115)
  Bottom Layer w20: v2(2605,2115) 2556.76,2115 2538.31,2133.45 2538.31,2208.31 2690,2360 3732.19,2360 3867.19,2225 R10.2
SIM_RXD: R3.1 U3.28 | length 453.2
  Top Layer w15: R3.1@3020,2620 v2(3020,2655) ; v2(3070,2965) 3071.52,2966.52 3154.74,2966.52 U3.28
  Bottom Layer w15: v2(3020,2655) 3023.83,2658.83 3023.83,2672.61 3025,2673.79 3025,2920 v2(3070,2965)
SIM_STATUS: U1.42 U3.24 | length 621.2
  Top Layer w20: U3.24 3046.61,2757.01 3054.33,2749.29 3125.71,2749.29 3200,2675 3200,2299.98 3199.32,2299.3 3199.32,2288.13 3197.64,2286.46 U1.42
SIM_TXD: R4.1 U3.27 | length 394
  Top Layer w15: v2(3085,2915) 3086.52,2916.52 3154.74,2916.52 U3.27 ; v2(3100,2655) 3100,2622.19 3102.19,2620 R4.1@3105,2620
  Bottom Layer w15: v2(3085,2915) 3065,2895 3065,2693.79 3100,2658.79 v2(3100,2655)
SIM_VDD: C11.1 U1.18 U2.1 | length 1715
  Top Layer w20: U1.18 2591.02,2069.92 2595.94,2065 v2(2600,2065) ; U2.1 3622.44,1932.44 v2(3665,1975)
  Bottom Layer w20: v2(2600,2065) 2602.87,2067.87 2621.55,2067.87 2650,2096.32 2650,2140 2745,2235 3286,2235 3365,2235 3430,2170 3430,2079 3504,2005 3630.94,2005 3660.94,1975 v2(3665,1975)
VCC: C3.1 C4.1 C5.1 C6.1 C7.1 C8.1 C13.1 C14.1 IC1.1 IC2.1 R6.2 R7.2 R11.2 R13.2 SW1.2 U1.34 U1.35 | length 4137.5
  Top Layer w20: 3185,1961.65 3235,1911.65 3235,1590 3392.5,1432.5 3392.5,1429.68 3402.19,1420 R7.2@3410,1420
  Top Layer w30: C3.1 C3.1@2064.94,1345 ; R11.2@2177.6,1382.6 IC2.1 ; R11.2 2180,1372.19 2152.82,1345 C3.1@2064.94,1345 ; R6.2@2350,1355 2345.31,1350.31 2345.31,1322.57 2327.74,1305 2104.94,1305 2079.94,1330 C3.1@2064.94,1345 ; R6.2 2353.19,1383.19 2353.19,1470.35 IC1.1
  Top Layer w50: 3036.73,1961.65 3185,1961.65
  Top Layer w80: SW1.2 C3.1@2079.94,1330
  Bottom Layer w50: C8.1 1885.59,1349.41 1889.53,1349.41 1923.94,1315 2568.94,1315 2664.41,1410.47 2664.41,1414.41 C4.1 C5.1 C6.1 ; C6.1@2665,1591.18 C7.1 2665,1904.92 cw(c2720,1904.92) 2720,1959.92 v4(3055,1959.92)
  other v4: 3030,1944.92 3030,1974.92
pads on no net: IC1.4 IC2.4 IC3.7 IC3.8 IC3.10 IC3.11 J2.4 U1.3 U1.4 U1.5 U1.6 U1.7 U1.9 U1.10 U1.11 U1.12 U1.14 U1.20 U1.22 U1.23 U1.24 U1.25 U1.26 U1.29 U1.38 U1.40 U2. U2.6 U3.4 U3.5 U3.6 U3.7 U3.11 U3.12 U3.13 U3.14 U3.16 U3.17 U3.18 U3.19 U3.20 U3.23 U3.32 U4.7 U4.8 U4.9 U4.10 U4.11 U4.12 U4.15

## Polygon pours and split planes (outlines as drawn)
GND on Bottom Layer "100" (solid, pour order 0): 1025,3705 1030,3700 2425,3700 2425,3496.25 2426.25,3495 3220,3495 3220,3700 4095,3700 4090,3695 4090,1030 1025,1030
GND on Top Layer "100" (solid, pour order 1): 1025,3705 1030,3700 2425,3700 2425,3496.25 2426.25,3495 3220,3495 3220,3700 4095,3700 4090,3695 4090,1030 1025,1030

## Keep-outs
Keep-Out Layer:
  lines w10: 1005,1010 1005,3730 2160,3730 2445,3730 2445,3510 3200,3510 3200,3730 4115,3730 4115,1010 1005,1010

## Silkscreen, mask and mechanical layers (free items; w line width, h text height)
Top Overlay:
  text "BOOT" at 1140,3170 h40
  text "RESET" at 1495,3170 h40
  text "ON-OFF" at 1830,3170 h40
  text "MASTER" at 1985,2475 h60
  text "SWITCH" at 1030,1235 h40
Bottom Overlay:
  text "BURNING ALARM" at 3040,2305 h80
  text "+5V ADAPTER" at 1593.2,2285 h40
  text "GND" at 1290,2090 h40
  text "+BAT" at 1325,1895 h40
  text "GND" at 1295,1695 h40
